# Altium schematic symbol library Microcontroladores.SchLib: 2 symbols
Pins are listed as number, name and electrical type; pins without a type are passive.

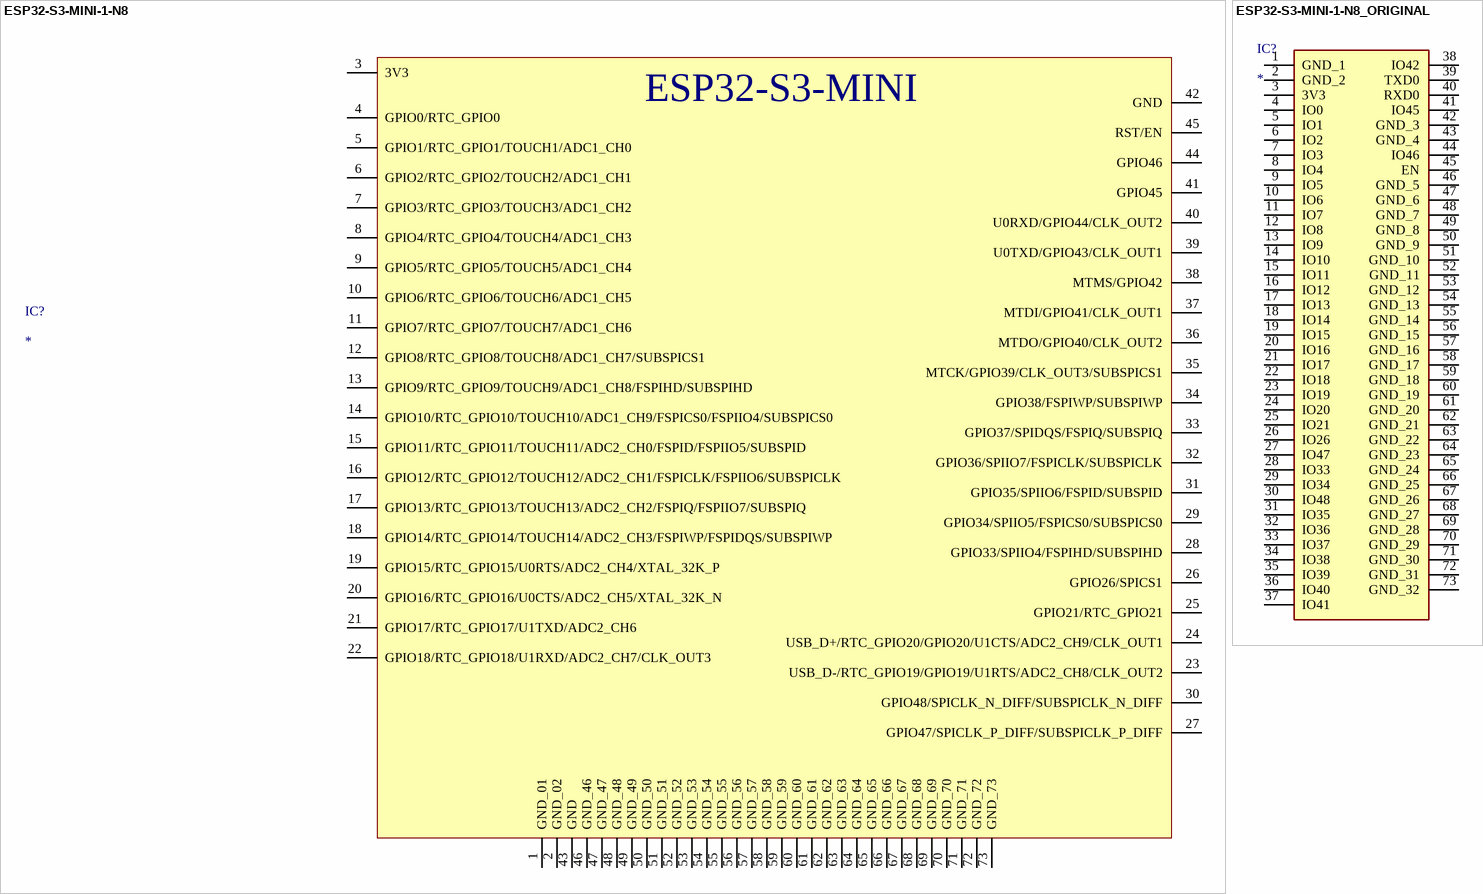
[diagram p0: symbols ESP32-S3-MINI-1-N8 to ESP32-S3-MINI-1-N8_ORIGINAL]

## ESP32-S3-MINI-1-N8
designator IC?
Integrated Circuit; Manufacturer_Name: Espressif Systems; Manufacturer_Part_Number: ESP32-S3-MINI-1-N8
footprint ESP32S3MINI1N8
pins: 1 GND_01, 2 GND_02, 3 3V3, 4 GPIO0/RTC_GPIO0, 5 GPIO1/RTC_GPIO1/TOUCH1/ADC1_CH0, 6 GPIO2/RTC_GPIO2/TOUCH2/ADC1_CH1, 7 GPIO3/RTC_GPIO3/TOUCH3/ADC1_CH2, 8 GPIO4/RTC_GPIO4/TOUCH4/ADC1_CH3, 9 GPIO5/RTC_GPIO5/TOUCH5/ADC1_CH4, 10 GPIO6/RTC_GPIO6/TOUCH6/ADC1_CH5, 11 GPIO7/RTC_GPIO7/TOUCH7/ADC1_CH6, 12 GPIO8/RTC_GPIO8/TOUCH8/ADC1_CH7/SUBSPICS1, 13 GPIO9/RTC_GPIO9/TOUCH9/ADC1_CH8/FSPIHD/SUBSPIHD, 14 GPIO10/RTC_GPIO10/TOUCH10/ADC1_CH9/FSPICS0/FSPIIO4/SUBSPICS0, 15 GPIO11/RTC_GPIO11/TOUCH11/ADC2_CH0/FSPID/FSPIIO5/SUBSPID, 16 GPIO12/RTC_GPIO12/TOUCH12/ADC2_CH1/FSPICLK/FSPIIO6/SUBSPICLK, 17 GPIO13/RTC_GPIO13/TOUCH13/ADC2_CH2/FSPIQ/FSPIIO7/SUBSPIQ, 18 GPIO14/RTC_GPIO14/TOUCH14/ADC2_CH3/FSPIWP/FSPIDQS/SUBSPIWP, 19 GPIO15/RTC_GPIO15/U0RTS/ADC2_CH4/XTAL_32K_P, 20 GPIO16/RTC_GPIO16/U0CTS/ADC2_CH5/XTAL_32K_N, 21 GPIO17/RTC_GPIO17/U1TXD/ADC2_CH6, 22 GPIO18/RTC_GPIO18/U1RXD/ADC2_CH7/CLK_OUT3, 23 USB_D-/RTC_GPIO19/GPIO19/U1RTS/ADC2_CH8/CLK_OUT2, 24 USB_D+/RTC_GPIO20/GPIO20/U1CTS/ADC2_CH9/CLK_OUT1, 25 GPIO21/RTC_GPIO21, 26 GPIO26/SPICS1, 27 GPIO47/SPICLK_P_DIFF/SUBSPICLK_P_DIFF, 28 GPIO33/SPIIO4/FSPIHD/SUBSPIHD, 29 GPIO34/SPIIO5/FSPICS0/SUBSPICS0, 30 GPIO48/SPICLK_N_DIFF/SUBSPICLK_N_DIFF, 31 GPIO35/SPIIO6/FSPID/SUBSPID, 32 GPIO36/SPIIO7/FSPICLK/SUBSPICLK, 33 GPIO37/SPIDQS/FSPIQ/SUBSPIQ, 34 GPIO38/FSPIWP/SUBSPIWP, 35 MTCK/GPIO39/CLK_OUT3/SUBSPICS1, 36 MTDO/GPIO40/CLK_OUT2, 37 MTDI/GPIO41/CLK_OUT1, 38 MTMS/GPIO42, 39 U0TXD/GPIO43/CLK_OUT1, 40 U0RXD/GPIO44/CLK_OUT2, 41 GPIO45, 42 GND, 43 GND, 44 GPIO46, 45 RST/EN, 46 GND_46, 47 GND_47, 48 GND_48, 49 GND_49, 50 GND_50, 51 GND_51, 52 GND_52, 53 GND_53, 54 GND_54, 55 GND_55, 56 GND_56, 57 GND_57, 58 GND_58, 59 GND_59, 60 GND_60, 61 GND_61, 62 GND_62, 63 GND_63, 64 GND_64, 65 GND_65, 66 GND_66, 67 GND_67, 68 GND_68, 69 GND_69, 70 GND_70, 71 GND_71, 72 GND_72, 73 GND_73

## ESP32-S3-MINI-1-N8_ORIGINAL
designator IC?
Integrated Circuit; Manufacturer_Name: Espressif Systems; Manufacturer_Part_Number: ESP32-S3-MINI-1-N8
footprint ESP32S3MINI1N8
pins: 1 GND_1, 2 GND_2, 3 3V3, 4 IO0, 5 IO1, 6 IO2, 7 IO3, 8 IO4, 9 IO5, 10 IO6, 11 IO7, 12 IO8, 13 IO9, 14 IO10, 15 IO11, 16 IO12, 17 IO13, 18 IO14, 19 IO15, 20 IO16, 21 IO17, 22 IO18, 23 IO19, 24 IO20, 25 IO21, 26 IO26, 27 IO47, 28 IO33, 29 IO34, 30 IO48, 31 IO35, 32 IO36, 33 IO37, 34 IO38, 35 IO39, 36 IO40, 37 IO41, 38 IO42, 39 TXD0, 40 RXD0, 41 IO45, 42 GND_3, 43 GND_4, 44 IO46, 45 EN, 46 GND_5, 47 GND_6, 48 GND_7, 49 GND_8, 50 GND_9, 51 GND_10, 52 GND_11, 53 GND_12, 54 GND_13, 55 GND_14, 56 GND_15, 57 GND_16, 58 GND_17, 59 GND_18, 60 GND_19, 61 GND_20, 62 GND_21, 63 GND_22, 64 GND_23, 65 GND_24, 66 GND_25, 67 GND_26, 68 GND_27, 69 GND_28, 70 GND_29, 71 GND_30, 72 GND_31, 73 GND_32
